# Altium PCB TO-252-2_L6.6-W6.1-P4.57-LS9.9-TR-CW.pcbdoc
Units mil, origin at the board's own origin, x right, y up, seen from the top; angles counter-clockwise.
Board outline 797.75 x 971.83 mil, 2 copper layers (Top Layer, Bottom Layer), stack 0 mil thick; 1 components, 0 nets, 3 pads, 0 vias.
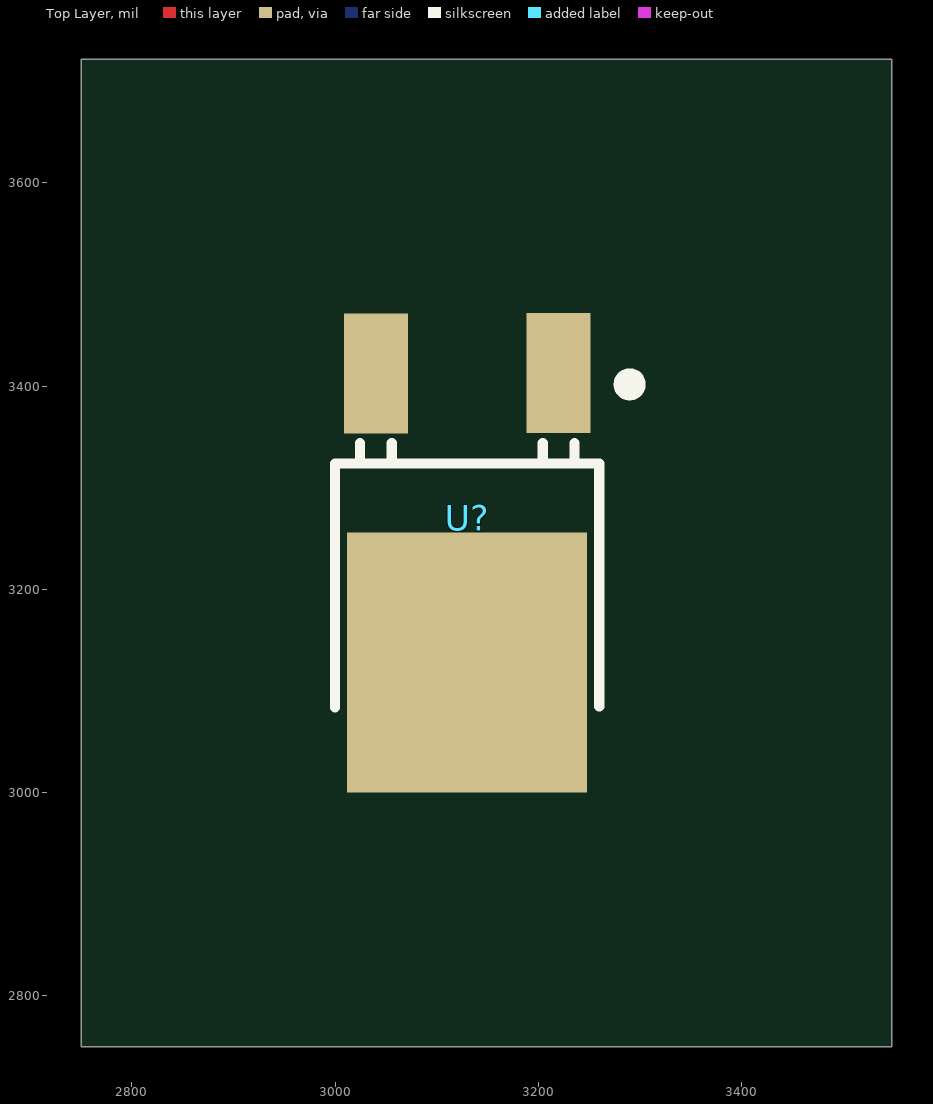
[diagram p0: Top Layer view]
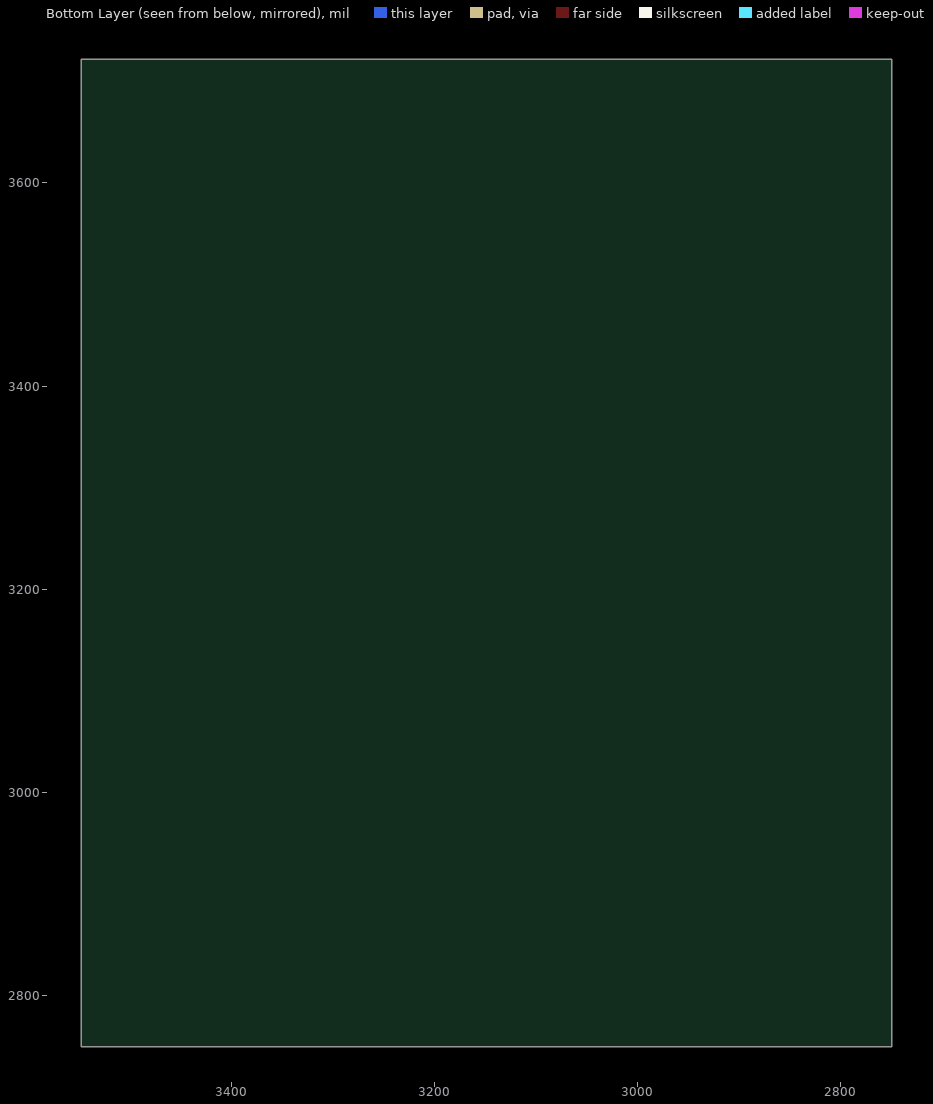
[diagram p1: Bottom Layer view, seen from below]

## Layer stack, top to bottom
Top Layer: signal copper (thickness not stored)
Bottom Layer: signal copper (thickness not stored)

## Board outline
3547.75,2750 2750,2750 2750,3721.83 3547.75,3721.83

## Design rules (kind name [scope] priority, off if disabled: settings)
PasteMaskExpansion "Paste Mask Expansion" [All] p1: expansion=0
SolderMaskExpansion "Solder Mask Expansion" [IsVia] p1: expansion=-1000 istentingtop=TRUE
SolderMaskExpansion "Solder Mask Expansion" [All] p2: expansion=2 istentingtop=FALSE

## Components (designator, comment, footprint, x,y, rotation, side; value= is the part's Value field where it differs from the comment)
U? "" TO-252-2_L6.6-W6.1-P4.57-LS9.9-TR-CW 3130,3270.36 r0 top

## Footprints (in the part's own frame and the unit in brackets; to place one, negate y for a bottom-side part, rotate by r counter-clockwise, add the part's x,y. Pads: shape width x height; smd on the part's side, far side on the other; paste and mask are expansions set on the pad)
TO-252-2_L6.6-W6.1-P4.57-LS9.9-TR-CW [mm]
  rect 1.6x3 smd: 1(2.285,3.617) 3(-2.285,3.611)
  rect 6x6.5 smd: 2(0,-3.617)
  silkscreen extent -3.3,-4.74 4.26,3.54

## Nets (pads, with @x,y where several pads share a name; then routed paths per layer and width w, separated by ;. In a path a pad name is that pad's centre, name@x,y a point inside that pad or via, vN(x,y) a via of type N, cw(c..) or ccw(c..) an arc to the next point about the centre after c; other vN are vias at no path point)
pads on no net: U?.1 U?.2 U?.3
